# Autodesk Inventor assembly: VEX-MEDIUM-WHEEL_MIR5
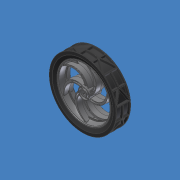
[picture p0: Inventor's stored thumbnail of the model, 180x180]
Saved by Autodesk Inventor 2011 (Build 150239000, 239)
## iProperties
Created: 2007-08
Part Number: VEX-MEDIUM-WHEEL_MIR5
Document SubType Name: Assembly
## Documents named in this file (3)
- C:\Data Folder\VEX 2011\Inventor Datasets\Unit 16\Components\VEX-MEDIUM-WHEEL_MIR5.iam
- C:\Data Folder\VEX 2011\Inventor Datasets\Unit 16\Components\MEDIUM-WHEEL-HUB_MIR5.ipt
- C:\Data Folder\VEX 2011\Inventor Datasets\Unit 16\Components\MEDIUM-WHEEL-TIRE_MIR4.ipt
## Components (2 placed, 2 different names)
1. MEDIUM-WHEEL-HUB_MIR5:1
2. MEDIUM-WHEEL-TIRE_MIR4:1
